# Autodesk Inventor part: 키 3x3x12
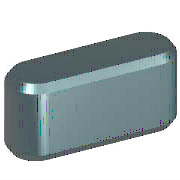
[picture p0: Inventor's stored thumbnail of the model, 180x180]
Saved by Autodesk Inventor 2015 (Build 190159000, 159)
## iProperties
Created: 2012-02
Part Number: 키 3x3x12
Material: 강철, 연강
Description: 키 및 해당 키홈
Document SubType Name: Modeling
Standard: KS B 1311
Designer: mduedu
Standards Organization: KS
Language: ko-KR
Size Designation: 3 x 3 x 12
Categories: <MemberInstance><Categories><Category DisplayName="샤프트 부품" InternalName="7f7aeb1f-a693-4053-b835-cee3144e0d98" Mnemonic="SHFT"><Category DisplayName="키" Interna
Density: 1 g/cm^3
Appearance: 노란색
IsCustomPart: 1
Author: mduedu
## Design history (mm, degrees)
workplane "Work Plane1"
workplane "Work Plane2"
sketch "스케치1"
  geometry: L1 (1.5, 1.5)-(10.5, 1.5); L2 (10.5, -1.5)-(1.5, -1.5); L3 (0, 9.4)-(0, -7.4) reference; L4 (-5, 0)-(30, 0) reference; L5 (12, 0)-(12, 7); A1 r 1.5 centre (1.5, 0) between (1.5, 1.5) and (1.5, -1.5); A2 r 1.5 centre (10.5, 0) between (10.5, -1.5) and (10.5, 1.5)
  constraints: 6 end point, 5 point on circle, 4 tangent, 3 point on line, 2 centre point, 1 horizontal, 1 parallel, 1 perpendicular
  dimensions: "d0" = 1.5 radius of A1 (= 0.5 x PB); "d13" = 1.5 radius of A2 (= 0.5 x PB); "d14" = 12 distance between parallel lines of L5 L3 (= NLG)
extrude "본체1" new body sketch "스케치1" taper "d3" = 0 deg; stored distance "d4" = 10
workplane "Work Plane3"
body "Solid1"
chamfer "모따기1" distance "d8" = 0.25 (= PHH); stored, may be unused: second distance "d9" = 0.25 (= PHH), angle "d15" = 45 deg
other parameters: "d1" = -1.8 (= -PNT), "d2" = 1.2 (= PH - PNT), "NLG" = 12 [user parameter; used in 3 equation terms], "PB" = 3 [user parameter; used in 2 equation terms], "PNT" = 1.8 [user parameter; used in 2 equation terms], "PH" = 3 [user parameter; used in 1 equation term], "PHH" = 0.25 [user parameter; used in 2 equation terms], "d10" = 0, "d16" = 0, "d17" = 0, "d18" = 0, "WDMIN" = 8 [user parameter], "PLB2" = 12 (= NLG) [user parameter], "PLB1" = 12 (= NLG) [user parameter], "RR" = 0.08 [user parameter], "PUEB" = 1.4 [user parameter]
